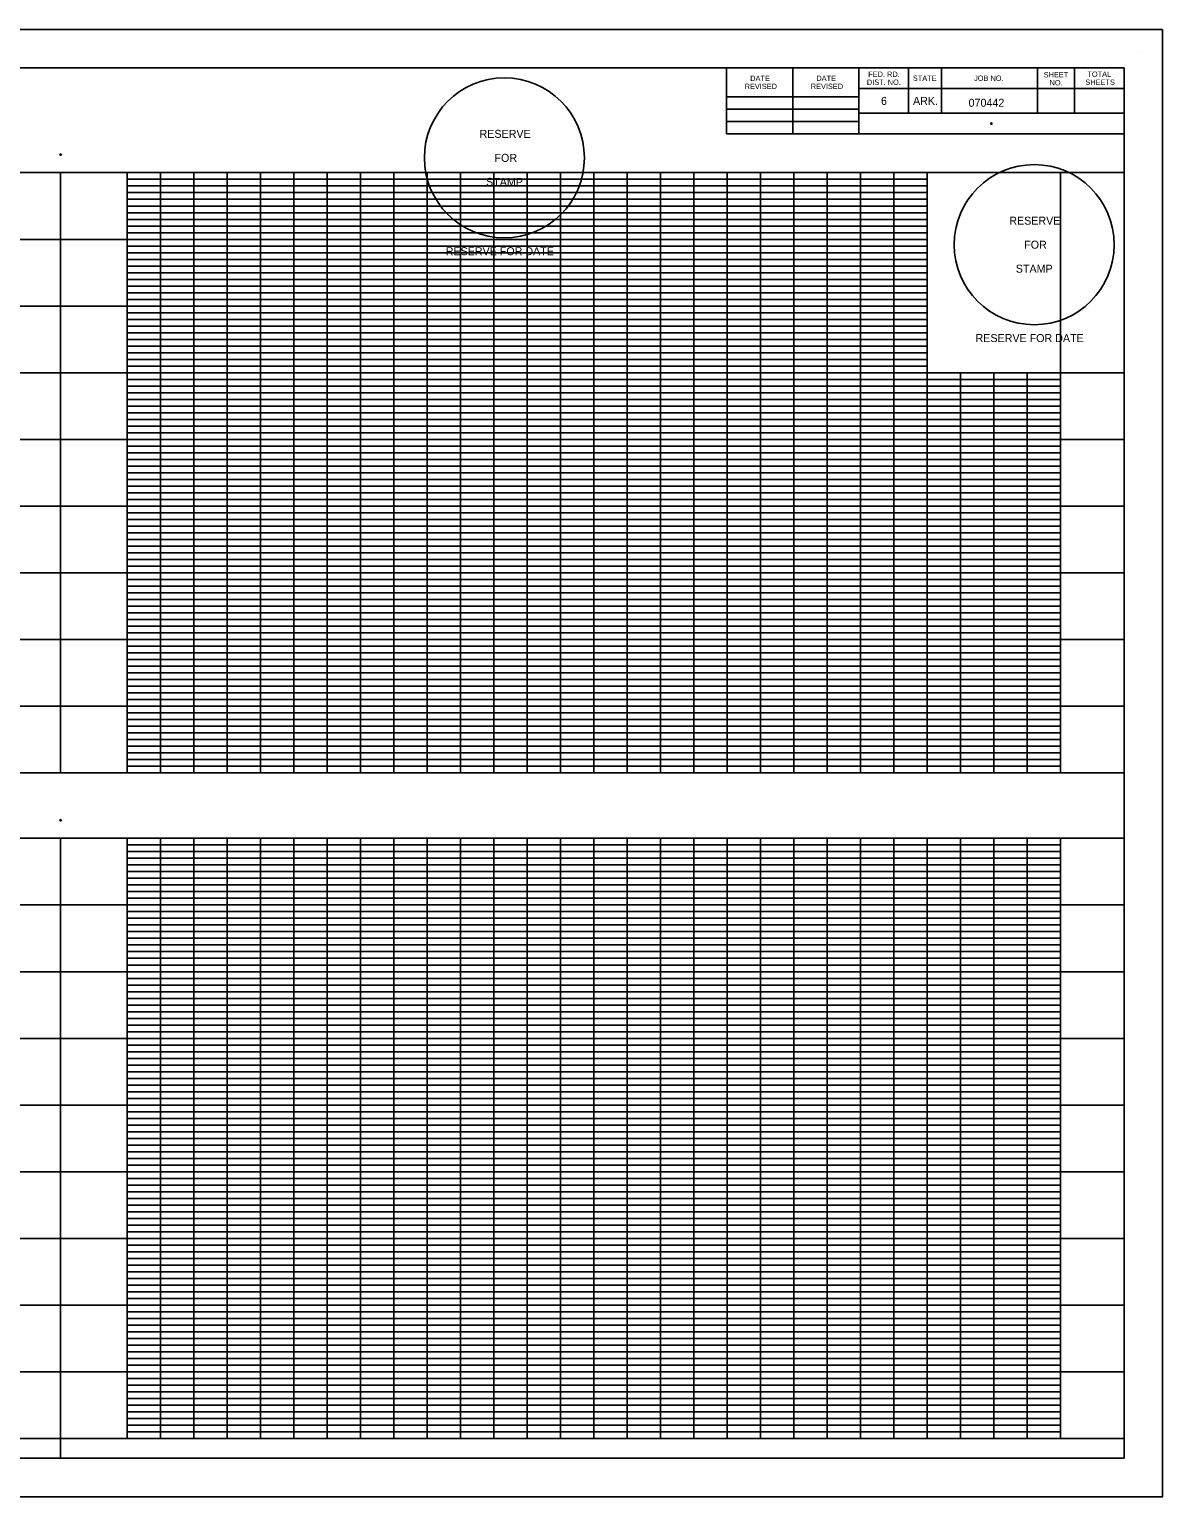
# Model space of a CAD drawing. Extents: x 1449378 to 1451078, y 2058337 to 2059437.
# Drawn here: x 1450228 to 1451078, y 2058337 to 2059437 of the extents above; entities that cross this region are included whole.
import ezdxf

# ---------------------------------------------------------------- set-up
doc = ezdxf.new("R2010")
doc.units = 0
for name, color, linetype in [('1', 7, 'Continuous'), ('G-ANNO-TEXT', 7, 'Continuous'), ('G-Border-Sheet', 7, 'Continuous'), ('G-Grid-Border-1', 7, 'Continuous'), ('G-Grid-Border-2', 7, 'Continuous'), ('G-Grid-Major-1', 7, 'Continuous'), ('G-Grid-Minor-1', 7, 'Continuous'), ('G-No Plot-Anchor', 7, 'Continuous'), ('G-No Plot-Stamp-1', 7, 'Continuous'), ('G-No Plot-Stamp-2', 7, 'Continuous'), ('G-Table-Major', 7, 'Continuous'), ('G-Table-Minor', 7, 'Continuous')]:
    doc.layers.add(name, color=color, linetype=linetype)

msp = doc.modelspace()

# ---------------------------------------------------------------- linework, layer by layer
at = {"layer": '1'}
msp.add_lwpolyline([(1451078.1, 2059436.5), (1449378.1, 2059436.5), (1449378.1, 2058336.5), (1451078.1, 2058336.5)], close=True, dxfattribs=at)
at = {"layer": 'G-ANNO-TEXT'}
msp.add_line((1451060.2, 2059419.2), (1451060.2, 2059419.2), dxfattribs=at)
at = {"layer": 'G-Border-Sheet'}
for p, q in [((1449453.9, 2059407.7), (1451049.3, 2059407.7)), ((1451049.3, 2058365.4), (1451049.3, 2059407.7)), ((1451049.3, 2058365.4), (1449453.9, 2058365.4))]:
    msp.add_line(p, q, dxfattribs=at)
at = {"layer": 'G-Grid-Border-1'}
for p, q in [((1450898.5, 2059329.1), (1449453.9, 2059329.1)), ((1450251.6, 2058879.1), (1450251.6, 2059329.1)), ((1451049.3, 2058879.1), (1449453.9, 2058879.1)), ((1451049.3, 2058830.1), (1449453.9, 2058830.1)), ((1450251.6, 2058380.1), (1450251.6, 2058830.1)), ((1451049.3, 2058380.1), (1449453.9, 2058380.1))]:
    msp.add_line(p, q, dxfattribs=at)
for points in [[(1450301.6, 2059329.1), (1450901.6, 2059329.1), (1450901.6, 2059179.1), (1451001.6, 2059179.1), (1451001.6, 2058879.1), (1450301.6, 2058879.1)], [(1450301.6, 2058830.1), (1451001.6, 2058830.1), (1451001.6, 2058380.1), (1450301.6, 2058380.1)]]:
    msp.add_lwpolyline(points, close=True, dxfattribs=at)
at = {"layer": 'G-Grid-Border-2'}
for p, q in [((1450501.6, 2059329.1), (1449453.9, 2059329.1)), ((1450251.6, 2058879.1), (1450251.6, 2059329.1)), ((1450501.6, 2059254.1), (1450501.6, 2059329.1)), ((1450501.6, 2059254.1), (1450501.6, 2059329.1)), ((1450651.6, 2059254.1), (1450651.6, 2059329.1)), ((1451049.3, 2059329.1), (1450651.6, 2059329.1)), ((1450651.6, 2059254.1), (1450651.6, 2059329.1)), ((1450501.6, 2059254.1), (1450651.6, 2059254.1)), ((1450501.6, 2059254.1), (1450651.6, 2059254.1)), ((1451001.6, 2058879.1), (1451001.6, 2059179.1)), ((1451049.3, 2058879.1), (1449453.9, 2058879.1)), ((1451049.3, 2058830.1), (1449453.9, 2058830.1)), ((1450251.6, 2058365.4), (1450251.6, 2058830.1)), ((1451001.6, 2058380.1), (1451001.6, 2058830.1)), ((1451049.3, 2058380.1), (1449453.9, 2058380.1))]:
    msp.add_line(p, q, dxfattribs=at)
for points in [[(1450301.6, 2059329.1), (1450501.6, 2059329.1), (1450501.6, 2059254.1), (1450651.6, 2059254.1), (1450651.6, 2059329.1), (1451001.6, 2059329.1), (1451001.6, 2058879.1), (1450301.6, 2058879.1)], [(1450301.6, 2058830.1), (1451001.6, 2058830.1), (1451001.6, 2058380.1), (1450301.6, 2058380.1)]]:
    msp.add_lwpolyline(points, close=True, dxfattribs=at)
msp.add_lwpolyline([(1451001.6, 2058830.1), (1451001.6, 2058380.1), (1449501.6, 2058380.1), (1449501.6, 2058830.1)], dxfattribs=at)
at = {"layer": 'G-Grid-Major-1'}
for p, q in [((1450301.6, 2058879.1), (1450301.6, 2059329.1)), ((1450351.6, 2058879.1), (1450351.6, 2059329.1)), ((1450401.6, 2058879.1), (1450401.6, 2059329.1)), ((1450451.6, 2058879.1), (1450451.6, 2059329.1)), ((1450501.6, 2058879.1), (1450501.6, 2059329.1)), ((1450551.6, 2058879.1), (1450551.6, 2059329.1)), ((1450601.6, 2058879.1), (1450601.6, 2059329.1)), ((1450651.6, 2058879.1), (1450651.6, 2059329.1)), ((1450701.6, 2058879.1), (1450701.6, 2059329.1)), ((1450751.6, 2058879.1), (1450751.6, 2059329.1)), ((1450801.6, 2058879.1), (1450801.6, 2059329.1)), ((1450851.6, 2058879.1), (1450851.6, 2059329.1)), ((1450901.6, 2058879.1), (1450901.6, 2059329.1)), ((1450901.6, 2059279.1), (1450201.6, 2059279.1)), ((1450901.6, 2059229.1), (1450201.6, 2059229.1)), ((1451049.3, 2059179.1), (1450201.6, 2059179.1)), ((1450951.6, 2058879.1), (1450951.6, 2059179.1)), ((1451049.3, 2059129.1), (1450201.6, 2059129.1)), ((1451049.3, 2059079.1), (1450201.6, 2059079.1)), ((1451049.3, 2059029.1), (1450201.6, 2059029.1)), ((1451049.3, 2058979.1), (1450201.6, 2058979.1)), ((1451049.3, 2058929.1), (1450201.6, 2058929.1)), ((1450301.6, 2058380.1), (1450301.6, 2058830.1)), ((1450351.6, 2058380.1), (1450351.6, 2058830.1)), ((1450401.6, 2058380.1), (1450401.6, 2058830.1)), ((1450451.6, 2058380.1), (1450451.6, 2058830.1)), ((1450501.6, 2058380.1), (1450501.6, 2058830.1)), ((1450551.6, 2058380.1), (1450551.6, 2058830.1)), ((1450601.6, 2058380.1), (1450601.6, 2058830.1)), ((1450651.6, 2058380.1), (1450651.6, 2058830.1)), ((1450701.6, 2058380.1), (1450701.6, 2058830.1)), ((1450751.6, 2058380.1), (1450751.6, 2058830.1)), ((1450801.6, 2058380.1), (1450801.6, 2058830.1)), ((1450851.6, 2058380.1), (1450851.6, 2058830.1)), ((1450901.6, 2058380.1), (1450901.6, 2058830.1)), ((1450951.6, 2058380.1), (1450951.6, 2058830.1)), ((1451049.3, 2058780.1), (1450201.6, 2058780.1)), ((1451049.3, 2058730.1), (1450201.6, 2058730.1)), ((1451049.3, 2058680.1), (1450201.6, 2058680.1)), ((1451049.3, 2058630.1), (1450201.6, 2058630.1)), ((1451049.3, 2058580.1), (1450201.6, 2058580.1)), ((1451049.3, 2058530.1), (1450201.6, 2058530.1)), ((1451049.3, 2058480.1), (1450201.6, 2058480.1)), ((1451049.3, 2058430.1), (1450201.6, 2058430.1))]:
    msp.add_line(p, q, dxfattribs=at)
at = {"layer": 'G-Grid-Minor-1'}
for p, q in [((1450901.6, 2059324.1), (1450301.6, 2059324.1)), ((1450326.6, 2058879.1), (1450326.6, 2059329.1)), ((1450376.6, 2058879.1), (1450376.6, 2059329.1)), ((1450426.6, 2058879.1), (1450426.6, 2059329.1)), ((1450476.6, 2058879.1), (1450476.6, 2059329.1)), ((1450526.6, 2058879.1), (1450526.6, 2059329.1)), ((1450576.6, 2058879.1), (1450576.6, 2059329.1)), ((1450626.6, 2058879.1), (1450626.6, 2059329.1)), ((1450676.6, 2058879.1), (1450676.6, 2059329.1)), ((1450726.6, 2058879.1), (1450726.6, 2059329.1)), ((1450776.6, 2058879.1), (1450776.6, 2059329.1)), ((1450826.6, 2058879.1), (1450826.6, 2059329.1)), ((1450876.6, 2058879.1), (1450876.6, 2059329.1)), ((1450901.6, 2059319.1), (1450301.6, 2059319.1)), ((1450901.6, 2059314.1), (1450301.6, 2059314.1)), ((1450901.6, 2059309.1), (1450301.6, 2059309.1)), ((1450901.6, 2059304.1), (1450301.6, 2059304.1)), ((1450901.6, 2059299.1), (1450301.6, 2059299.1)), ((1450901.6, 2059294.1), (1450301.6, 2059294.1)), ((1450901.6, 2059289.1), (1450301.6, 2059289.1)), ((1450901.6, 2059284.1), (1450301.6, 2059284.1)), ((1450901.6, 2059274.1), (1450301.6, 2059274.1)), ((1450901.6, 2059269.1), (1450301.6, 2059269.1)), ((1450901.6, 2059264.1), (1450301.6, 2059264.1)), ((1450901.6, 2059259.1), (1450301.6, 2059259.1)), ((1450901.6, 2059254.1), (1450301.6, 2059254.1)), ((1450901.6, 2059249.1), (1450301.6, 2059249.1)), ((1450901.6, 2059244.1), (1450301.6, 2059244.1)), ((1450901.6, 2059239.1), (1450301.6, 2059239.1)), ((1450901.6, 2059234.1), (1450301.6, 2059234.1)), ((1450901.6, 2059224.1), (1450301.6, 2059224.1)), ((1450901.6, 2059219.1), (1450301.6, 2059219.1)), ((1450901.6, 2059214.1), (1450301.6, 2059214.1)), ((1450901.6, 2059209.1), (1450301.6, 2059209.1)), ((1450901.6, 2059204.1), (1450301.6, 2059204.1)), ((1450901.6, 2059199.1), (1450301.6, 2059199.1)), ((1450901.6, 2059194.1), (1450301.6, 2059194.1)), ((1450901.6, 2059189.1), (1450301.6, 2059189.1)), ((1450901.6, 2059184.1), (1450301.6, 2059184.1)), ((1450926.6, 2058879.1), (1450926.6, 2059179.1)), ((1450976.6, 2058879.1), (1450976.6, 2059179.1)), ((1451001.6, 2059174.1), (1450301.6, 2059174.1)), ((1451001.6, 2059169.1), (1450301.6, 2059169.1)), ((1451001.6, 2059164.1), (1450301.6, 2059164.1)), ((1451001.6, 2059159.1), (1450301.6, 2059159.1)), ((1451001.6, 2059154.1), (1450301.6, 2059154.1)), ((1451001.6, 2059149.1), (1450301.6, 2059149.1)), ((1451001.6, 2059144.1), (1450301.6, 2059144.1)), ((1451001.6, 2059139.1), (1450301.6, 2059139.1)), ((1451001.6, 2059134.1), (1450301.6, 2059134.1)), ((1451001.6, 2059124.1), (1450301.6, 2059124.1)), ((1451001.6, 2059119.1), (1450301.6, 2059119.1)), ((1451001.6, 2059114.1), (1450301.6, 2059114.1)), ((1451001.6, 2059109.1), (1450301.6, 2059109.1)), ((1451001.6, 2059104.1), (1450301.6, 2059104.1)), ((1451001.6, 2059099.1), (1450301.6, 2059099.1)), ((1451001.6, 2059094.1), (1450301.6, 2059094.1)), ((1451001.6, 2059089.1), (1450301.6, 2059089.1)), ((1451001.6, 2059084.1), (1450301.6, 2059084.1)), ((1451001.6, 2059074.1), (1450301.6, 2059074.1)), ((1451001.6, 2059069.1), (1450301.6, 2059069.1)), ((1451001.6, 2059064.1), (1450301.6, 2059064.1)), ((1451001.6, 2059059.1), (1450301.6, 2059059.1)), ((1451001.6, 2059054.1), (1450301.6, 2059054.1)), ((1451001.6, 2059049.1), (1450301.6, 2059049.1)), ((1451001.6, 2059044.1), (1450301.6, 2059044.1)), ((1451001.6, 2059039.1), (1450301.6, 2059039.1)), ((1451001.6, 2059034.1), (1450301.6, 2059034.1)), ((1451001.6, 2059024.1), (1450301.6, 2059024.1)), ((1451001.6, 2059019.1), (1450301.6, 2059019.1)), ((1451001.6, 2059014.1), (1450301.6, 2059014.1)), ((1451001.6, 2059009.1), (1450301.6, 2059009.1)), ((1451001.6, 2059004.1), (1450301.6, 2059004.1)), ((1451001.6, 2058999.1), (1450301.6, 2058999.1)), ((1451001.6, 2058994.1), (1450301.6, 2058994.1)), ((1451001.6, 2058989.1), (1450301.6, 2058989.1)), ((1451001.6, 2058984.1), (1450301.6, 2058984.1)), ((1451001.6, 2058974.1), (1450301.6, 2058974.1)), ((1451001.6, 2058969.1), (1450301.6, 2058969.1)), ((1451001.6, 2058964.1), (1450301.6, 2058964.1)), ((1451001.6, 2058959.1), (1450301.6, 2058959.1)), ((1451001.6, 2058954.1), (1450301.6, 2058954.1)), ((1451001.6, 2058949.1), (1450301.6, 2058949.1)), ((1451001.6, 2058944.1), (1450301.6, 2058944.1)), ((1451001.6, 2058939.1), (1450301.6, 2058939.1)), ((1451001.6, 2058934.1), (1450301.6, 2058934.1)), ((1451001.6, 2058924.1), (1450301.6, 2058924.1)), ((1451001.6, 2058919.1), (1450301.6, 2058919.1)), ((1451001.6, 2058914.1), (1450301.6, 2058914.1)), ((1451001.6, 2058909.1), (1450301.6, 2058909.1)), ((1451001.6, 2058904.1), (1450301.6, 2058904.1)), ((1451001.6, 2058899.1), (1450301.6, 2058899.1)), ((1451001.6, 2058894.1), (1450301.6, 2058894.1)), ((1451001.6, 2058889.1), (1450301.6, 2058889.1)), ((1451001.6, 2058884.1), (1450301.6, 2058884.1)), ((1450326.6, 2058380.1), (1450326.6, 2058830.1)), ((1450376.6, 2058380.1), (1450376.6, 2058830.1)), ((1450426.6, 2058380.1), (1450426.6, 2058830.1)), ((1450476.6, 2058380.1), (1450476.6, 2058830.1)), ((1450526.6, 2058380.1), (1450526.6, 2058830.1)), ((1450576.6, 2058380.1), (1450576.6, 2058830.1)), ((1450626.6, 2058380.1), (1450626.6, 2058830.1)), ((1450676.6, 2058380.1), (1450676.6, 2058830.1)), ((1450726.6, 2058380.1), (1450726.6, 2058830.1)), ((1450776.6, 2058380.1), (1450776.6, 2058830.1)), ((1450826.6, 2058380.1), (1450826.6, 2058830.1)), ((1450876.6, 2058380.1), (1450876.6, 2058830.1)), ((1450926.6, 2058380.1), (1450926.6, 2058830.1)), ((1450976.6, 2058380.1), (1450976.6, 2058830.1)), ((1451001.6, 2058825.1), (1450301.6, 2058825.1)), ((1451001.6, 2058820.1), (1450301.6, 2058820.1)), ((1451001.6, 2058815.1), (1450301.6, 2058815.1)), ((1451001.6, 2058810.1), (1450301.6, 2058810.1)), ((1451001.6, 2058805.1), (1450301.6, 2058805.1)), ((1451001.6, 2058800.1), (1450301.6, 2058800.1)), ((1451001.6, 2058795.1), (1450301.6, 2058795.1)), ((1451001.6, 2058790.1), (1450301.6, 2058790.1)), ((1451001.6, 2058785.1), (1450301.6, 2058785.1)), ((1451001.6, 2058775.1), (1450301.6, 2058775.1)), ((1451001.6, 2058770.1), (1450301.6, 2058770.1)), ((1451001.6, 2058765.1), (1450301.6, 2058765.1)), ((1451001.6, 2058760.1), (1450301.6, 2058760.1)), ((1451001.6, 2058755.1), (1450301.6, 2058755.1)), ((1451001.6, 2058750.1), (1450301.6, 2058750.1)), ((1451001.6, 2058745.1), (1450301.6, 2058745.1)), ((1451001.6, 2058740.1), (1450301.6, 2058740.1)), ((1451001.6, 2058735.1), (1450301.6, 2058735.1)), ((1451001.6, 2058725.1), (1450301.6, 2058725.1)), ((1451001.6, 2058720.1), (1450301.6, 2058720.1)), ((1451001.6, 2058715.1), (1450301.6, 2058715.1)), ((1451001.6, 2058710.1), (1450301.6, 2058710.1)), ((1451001.6, 2058705.1), (1450301.6, 2058705.1)), ((1451001.6, 2058700.1), (1450301.6, 2058700.1)), ((1451001.6, 2058695.1), (1450301.6, 2058695.1)), ((1451001.6, 2058690.1), (1450301.6, 2058690.1)), ((1451001.6, 2058685.1), (1450301.6, 2058685.1)), ((1451001.6, 2058675.1), (1450301.6, 2058675.1)), ((1451001.6, 2058670.1), (1450301.6, 2058670.1)), ((1451001.6, 2058665.1), (1450301.6, 2058665.1)), ((1451001.6, 2058660.1), (1450301.6, 2058660.1)), ((1451001.6, 2058655.1), (1450301.6, 2058655.1)), ((1451001.6, 2058650.1), (1450301.6, 2058650.1)), ((1451001.6, 2058645.1), (1450301.6, 2058645.1)), ((1451001.6, 2058640.1), (1450301.6, 2058640.1)), ((1451001.6, 2058635.1), (1450301.6, 2058635.1)), ((1451001.6, 2058625.1), (1450301.6, 2058625.1)), ((1451001.6, 2058620.1), (1450301.6, 2058620.1)), ((1451001.6, 2058615.1), (1450301.6, 2058615.1)), ((1451001.6, 2058610.1), (1450301.6, 2058610.1)), ((1451001.6, 2058605.1), (1450301.6, 2058605.1)), ((1451001.6, 2058600.1), (1450301.6, 2058600.1)), ((1451001.6, 2058595.1), (1450301.6, 2058595.1)), ((1451001.6, 2058590.1), (1450301.6, 2058590.1)), ((1451001.6, 2058585.1), (1450301.6, 2058585.1)), ((1451001.6, 2058575.1), (1450301.6, 2058575.1)), ((1451001.6, 2058570.1), (1450301.6, 2058570.1)), ((1451001.6, 2058565.1), (1450301.6, 2058565.1)), ((1451001.6, 2058560.1), (1450301.6, 2058560.1)), ((1451001.6, 2058555.1), (1450301.6, 2058555.1)), ((1451001.6, 2058550.1), (1450301.6, 2058550.1)), ((1451001.6, 2058545.1), (1450301.6, 2058545.1)), ((1451001.6, 2058540.1), (1450301.6, 2058540.1)), ((1451001.6, 2058535.1), (1450301.6, 2058535.1)), ((1451001.6, 2058525.1), (1450301.6, 2058525.1)), ((1451001.6, 2058520.1), (1450301.6, 2058520.1)), ((1451001.6, 2058515.1), (1450301.6, 2058515.1)), ((1451001.6, 2058510.1), (1450301.6, 2058510.1)), ((1451001.6, 2058505.1), (1450301.6, 2058505.1)), ((1451001.6, 2058500.1), (1450301.6, 2058500.1)), ((1451001.6, 2058495.1), (1450301.6, 2058495.1)), ((1451001.6, 2058490.1), (1450301.6, 2058490.1)), ((1451001.6, 2058485.1), (1450301.6, 2058485.1)), ((1451001.6, 2058475.1), (1450301.6, 2058475.1)), ((1451001.6, 2058470.1), (1450301.6, 2058470.1)), ((1451001.6, 2058465.1), (1450301.6, 2058465.1)), ((1451001.6, 2058460.1), (1450301.6, 2058460.1)), ((1451001.6, 2058455.1), (1450301.6, 2058455.1)), ((1451001.6, 2058450.1), (1450301.6, 2058450.1)), ((1451001.6, 2058445.1), (1450301.6, 2058445.1)), ((1451001.6, 2058440.1), (1450301.6, 2058440.1)), ((1451001.6, 2058435.1), (1450301.6, 2058435.1)), ((1451001.6, 2058425.1), (1450301.6, 2058425.1)), ((1451001.6, 2058420.1), (1450301.6, 2058420.1)), ((1451001.6, 2058415.1), (1450301.6, 2058415.1)), ((1451001.6, 2058410.1), (1450301.6, 2058410.1)), ((1451001.6, 2058405.1), (1450301.6, 2058405.1)), ((1451001.6, 2058400.1), (1450301.6, 2058400.1)), ((1451001.6, 2058395.1), (1450301.6, 2058395.1)), ((1451001.6, 2058390.1), (1450301.6, 2058390.1)), ((1451001.6, 2058385.1), (1450301.6, 2058385.1))]:
    msp.add_line(p, q, dxfattribs=at)
msp.add_lwpolyline([(1451001.6, 2059179.1), (1451001.6, 2058879.1), (1449501.6, 2058879.1), (1449501.6, 2059329.1)], dxfattribs=at)
at = {"layer": 'G-No Plot-Anchor'}
for centre in [(1450949.7, 2059365.9), (1450251.6, 2059342.6), (1450251.6, 2058843.6)]:
    msp.add_circle(centre, 0.5, dxfattribs=at)
at = {"layer": 'G-No Plot-Stamp-1'}
msp.add_circle((1450981.8, 2059275.1), 60, dxfattribs=at)
at = {"layer": 'G-No Plot-Stamp-2'}
msp.add_circle((1450584.4, 2059340.2), 60, dxfattribs=at)
at = {"layer": 'G-Table-Major'}
for p, q in [((1450750.9, 2059358.2), (1450750.9, 2059407.7)), ((1450850.2, 2059407.7), (1450850.2, 2059358.1)), ((1450750.9, 2059386), (1450850.2, 2059386)), ((1451049.3, 2059358.1), (1450750.9, 2059358.1))]:
    msp.add_line(p, q, dxfattribs=at)
at = {"layer": 'G-Table-Minor'}
for p, q in [((1450800.7, 2059358.2), (1450800.7, 2059407.7)), ((1450887.4, 2059407.7), (1450887.4, 2059373.7)), ((1450912.2, 2059407.7), (1450912.2, 2059373.7)), ((1450984.3, 2059407.7), (1450984.3, 2059373.7)), ((1451012.1, 2059407.7), (1451012.1, 2059373.7)), ((1451049.3, 2059392.1), (1450850.2, 2059392.1)), ((1451049.3, 2059393.1), (1451049.3, 2059393.1)), ((1450750.9, 2059376.6), (1450850.2, 2059376.6)), ((1450750.9, 2059367.5), (1450850.2, 2059367.5)), ((1451049.3, 2059373.7), (1450850.2, 2059373.7))]:
    msp.add_line(p, q, dxfattribs=at)

# ---------------------------------------------------------------- texts
at = {"layer": 'G-ANNO-TEXT'}
for s, height, p in [('DATE', 4, (1450768.8, 2059397.8)), ('DATE', 4, (1450818.4, 2059397.8)), ('DIST. NO.', 4, (1450856.3, 2059394.9)), ('FED. RD.', 4, (1450857.3, 2059400.9)), ('STATE', 4, (1450890.8, 2059397.9)), ('JOB NO.', 4, (1450936.7, 2059397.9)), ('SHEET', 4, (1450988.9, 2059400.5)), ('NO.', 4, (1450993.3, 2059394.5)), ('SHEETS', 4, (1451020.2, 2059394.9)), ('TOTAL', 4, (1451021.7, 2059400.9)), ('REVISED', 4, (1450764.6, 2059391.8)), ('REVISED', 4, (1450814.2, 2059391.8)), ('6', 6, (1450866.9, 2059379.9)), ('ARK.', 6, (1450890.9, 2059379.9)), ('070442', 6, (1450932.6, 2059378.5))]:
    msp.add_text(s, height=height, dxfattribs=at).set_placement(p)
at = {"layer": 'G-No Plot-Stamp-1'}
for s, p in [('RESERVE', (1450963.1, 2059290.1)), ('FOR ', (1450974.3, 2059272.1)), ('STAMP', (1450968, 2059254.1)), ('RESERVE FOR DATE', (1450937.8, 2059202.1))]:
    msp.add_text(s, height=6, dxfattribs=at).set_placement(p)
at = {"layer": 'G-No Plot-Stamp-2'}
for s, p in [('RESERVE', (1450565.8, 2059355.2)), ('FOR ', (1450577, 2059337.2)), ('STAMP', (1450570.7, 2059319.2)), ('RESERVE FOR DATE', (1450540.4, 2059267.2)), ('RESERVE FOR DATE', (1450540.4, 2059267.2))]:
    msp.add_text(s, height=6, dxfattribs=at).set_placement(p)

doc.saveas('drawing.dxf')
